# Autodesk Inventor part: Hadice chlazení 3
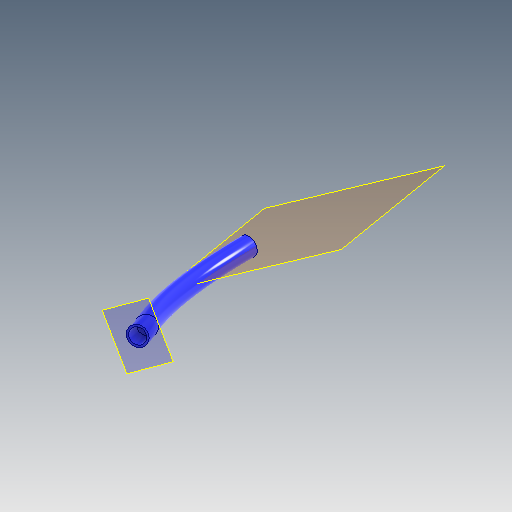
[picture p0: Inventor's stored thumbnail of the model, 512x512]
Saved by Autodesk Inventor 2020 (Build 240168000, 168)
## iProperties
Created: 2025-04
Part Number: Hadice chlazení 3
Material: Polyetylen, S nízkou hustotou
Document SubType Name: Modeling
Designer: doma
Density: 0.894 g/cm^3
Appearance: Modrá – nástěnná malba – lesklá
Mass: 2.5838 g
Surface Area: 58.3685 cm^2
Volume: 2.89015 cm^3
Author: doma
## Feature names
1. Tažení1
## Parameters: d1 = 8 mm, d2 = 0, d3 = 0
